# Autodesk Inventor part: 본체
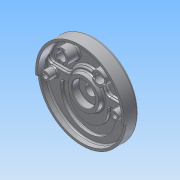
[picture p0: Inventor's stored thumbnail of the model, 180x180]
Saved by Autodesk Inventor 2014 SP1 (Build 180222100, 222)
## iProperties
Created: 2015-05
Part Number: 본체
Material: 알루미늄 6061
Document SubType Name: Modeling
Designer: 상담실
Density: 2.71 g/cm^3
Appearance: 알루미늄 - 평지
Mass: 1081.88 g
Surface Area: 1044.41 cm^2
Volume: 399.218 cm^3
Author: 상담실
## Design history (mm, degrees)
sketch "스케치1"
  geometry: C1 r 95 at (0, 0); 1 further point
  constraints: 1 centre point, 1 coincident
  dimensions: "d0" = 190 diameter of C1
extrude "돌출1" new body sketch "스케치1" distance "d1" = 32; taper "d2" = 0 deg
sketch "스케치2"
  geometry: C1 r 95 at (0, 0) reference; C2 r 90 at (0, 0)
  constraints: 1 centre point, 1 coincident
  dimensions: "d3" = 180 diameter of C2
extrude "돌출2" cut sketch "스케치2" distance "d4" = 25; taper "d5" = 0 deg
sketch "스케치3"
  geometry: L1 (-94.638, -8.28)-(-89.658, -7.844); L2 (89.658, -7.844)-(94.638, -8.28); L3 (-95, 0)-(95, 0); A1 r 90 centre (0, 0) between (-89.658, -7.844) and (89.658, -7.844) reference; A2 r 95 centre (0, 0) between (-94.638, -8.28) and (94.638, -8.28) reference; 2 further points
  constraints: 6 end point, 6 point on circle, 2 midpoint, 2 point on line, 1 coincident, 1 horizontal
  dimensions: "d6" = 5 deg angle of L3 L1; "d7" = 5 deg angle of L2 L3
extrude "돌출3" cut sketch "스케치3" distance "d8" = 5; taper "d9" = 0 deg
sketch "스케치4"
  geometry: L1 (-89.196, 12)-(-40.249, 12); L2 (40.249, 12)-(89.196, 12); A1 r 90 centre (0, 0) between (-89.196, 12) and (89.196, 12) reference; A2 r 42 centre (0, 0) between (40.249, 12) and (-40.249, 12)
  constraints: 4 end point, 4 point on circle, 2 horizontal, 1 centre point, 1 coincident, 1 collinear
  dimensions: "d10" = 84 diameter of A2; "d11" = 12 distance from line of A1.centre L1
extrude "돌출4" join sketch "스케치4" distance "d12" = 7; taper "d13" = 0 deg
sketch "스케치5"
  geometry: C1 r 35 at (0, 0); A1 r 42 centre (0, 0) between (40.249, 12) and (-40.249, 12) reference
  constraints: 1 centre point, 1 coincident
  dimensions: "d14" = 70 diameter of C1
extrude "돌출5" join sketch "스케치5" distance "d15" = 10; taper "d16" = -10 deg
sketch "스케치6"
  geometry: C1 r 95 at (0, 0) reference; C2 r 25 at (0, 0)
  constraints: 1 centre point, 1 coincident
  dimensions: "d17" = 50 diameter of C2
extrude "돌출6" join sketch "스케치6" distance "d18" = 12; taper "d19" = -15 deg
hole "구멍1" diameter "d22" = 23; stored, may be unused: countersink angle "d26" = 90 deg, drill point angle "d28" = 118 deg; dims "d20" = 10, "d21" = 10, "d23" = 6, "d24" = 4, "d25" = 2, "d27" = 8
fillet "모깎기1" dims "d31" = 10
fillet "모깎기2" dims "d32" = 3
fillet "모깎기3" dims "d33" = 5
sketch "스케치7"
  geometry: C1 r 9 at (-74, 0); C2 r 9 at (74, 0); A1 r 87 centre (0, 0) between (-86.059, 12.759) and (86.059, 12.759) reference
  constraints: 2 centre point, 2 horizontal alignment
  dimensions: "d34" = 18 diameter of C1; "d35" = 18 diameter of C2; "d36" = 148 distance of C2.centre C1.centre; "d37" = 74 distance of A1.centre C1.centre (= 0.5 x d36)
extrude "돌출7" join sketch "스케치7" distance "d38" = 18; taper "d39" = 0 deg
hole "구멍2" diameter "d42" = 11; stored, may be unused: countersink angle "d46" = 90 deg, drill point angle "d48" = 118 deg; dims "d40" = 10, "d41" = 10, "d43" = 6, "d44" = 4, "d45" = 2, "d47" = 8
hole "구멍3" diameter "d51" = 11; stored, may be unused: countersink angle "d55" = 90 deg, drill point angle "d57" = 118 deg; dims "d49" = 10, "d50" = 10, "d52" = 6, "d53" = 4, "d54" = 2, "d56" = 8
hole "구멍4" diameter "d60" = 18; stored, may be unused: countersink angle "d64" = 90 deg, drill point angle "d66" = 0 deg; dims "d61" = 6, "d62" = 4, "d63" = 2, "d65" = 11, "d67" = 10, "d68" = 10
hole "구멍5" diameter "d71" = 18; stored, may be unused: countersink angle "d75" = 90 deg, drill point angle "d77" = 0 deg; dims "d69" = 10, "d70" = 10, "d72" = 6, "d73" = 4, "d74" = 2, "d76" = 11
sketch "스케치8"
  geometry: C1 r 15 at (-40, 52); C2 r 15 at (40, 52); A1 r 45 centre (0, 0) between (40.774, 19.038) and (-40.774, 19.038) reference
  constraints: 2 centre point, 1 horizontal alignment
  dimensions: "d78" = 30 diameter of C1; "d79" = 30 diameter of C2; "d80" = 52 vertical distance of A1.centre C1.centre; "d81" = 80 distance of C2.centre C1.centre; "d82" = 40 horizontal distance of A1.centre C1.centre (= 0.5 x d81)
extrude "돌출8" join sketch "스케치8" distance "d83" = 25; taper "d84" = 0 deg
hole "구멍6" diameter "d87" = 20; stored, may be unused: countersink angle "d91" = 90 deg, drill point angle "d93" = 0 deg; dims "d85" = 10, "d86" = 10, "d88" = 6, "d89" = 4, "d90" = 2, "d92" = 11
hole "구멍7" diameter "d96" = 20; stored, may be unused: countersink angle "d100" = 90 deg, drill point angle "d102" = 0 deg; dims "d94" = 10, "d95" = 10, "d97" = 6, "d98" = 4, "d99" = 2, "d101" = 11
sketch "스케치9"
  geometry: L1 (-6, -15)-(6, -15); L2 (6, -15)-(6, 15); L3 (6, 15)-(-6, 15); L4 (-6, 15)-(-6, -15); L5 (-6, -15)-(6, 15); L6 (6, -15)-(-6, 15); L7 (65, -6)-(95, -6); L8 (95, -6)-(95, 6); L9 (95, 6)-(65, 6); L10 (65, 6)-(65, -6); L11 (65, -6)-(95, 6); L12 (95, -6)-(65, 6); C1 r 15 at (0, 0) reference; C2 r 10 at (80, 0) reference; 1 further point
  constraints: 24 end point, 4 midpoint, 4 parallel, 2 horizontal, 2 perpendicular
  dimensions: "d103" = 12 distance of L3.end L2.end; "d104" = 30 distance of L2.end L1.end; "d105" = 30 distance of L9.end L8.end; "d106" = 12 distance of L8.end L7.end
extrude "돌출9" cut sketch "스케치9" distance "d107" = 3; taper "d108" = 0 deg
sketch "스케치10"
  geometry: L1 (-76.916, 9)-(-74, 9) reference; L2 (-59, -19)-(-41, -19); L3 (41, -19)-(59, -19); L4 (-59, -19)-(-59, -14); L5 (-41, -14)-(-41, -19); L6 (41, -19)-(41, -14); L7 (59, -14)-(59, -19); C1 r 37.517 at (0, 0) reference; A1 r 59 centre (0, -19) between (-59, -19) and (59, -19); A2 r 41 centre (0, -19) between (-41, -19) and (41, -19); A3 r 9 centre (-50, -14) between (-41, -14) and (-59, -14); A4 r 9 centre (50, -14) between (59, -14) and (41, -14); 2 further points
  constraints: 12 end point, 8 point on circle, 8 tangent, 5 parallel, 4 centre point, 3 coincident, 1 horizontal alignment, 1 perpendicular, 1 vertical alignment
  dimensions: "d110" = 118 diameter of A1; "d111" = 82 diameter of A2; "d112" = 19 distance of C1.centre A1.centre; "d114" = 5 vertical distance of A1.centre A3.centre
extrude "돌출10" cut sketch "스케치10" distance "d115" = 7; taper "d116" = 0 deg
hole "구멍8" diameter "d119" = 50; stored, may be unused: countersink angle "d123" = 90 deg, drill point angle "d125" = 0 deg; dims "d117" = 10, "d118" = 10, "d120" = 6, "d121" = 4, "d122" = 2, "d124" = 15
chamfer "모따기1" distance "d126" = 1; stored, may be unused: second distance "d127" = 2, angle "d128" = 45 deg
sketch "스케치11"
  geometry: L1 (95, 0)-(-95, 0); L2 (47.244, 47.244)-(39.44, 39.44); L3 (-39.44, 39.44)-(-47.244, 47.244); C1 r 25 at (0, 0) reference; C2 r 90 at (0, 0) reference; A1 r 51 centre (0, 0) between (32.699, 39.138) and (-32.699, 39.138); A2 r 72 centre (0, 0) between (46.97, 54.569) and (-46.97, 54.569); A3 r 5 centre (-43.709, 50.78) between (-46.97, 54.569) and (-47.244, 47.244); A4 r 5 centre (-35.904, 42.975) between (-39.44, 39.44) and (-32.699, 39.138); A5 r 5 centre (35.904, 42.975) between (32.699, 39.138) and (39.44, 39.44); A6 r 5 centre (43.709, 50.78) between (47.244, 47.244) and (46.97, 54.569); 5 further points
  constraints: 16 point on circle, 8 tangent, 6 centre point, 6 end point, 6 point on line, 3 coincident, 3 equal radius, 1 horizontal, 1 midpoint
  dimensions: "d130" = 102 diameter of A1; "d131" = 190 distance of L1.start L1.end; "d133" = 45 deg angle of L2 L1; "d134" = 45 deg angle of L3 L1; "d135" = 72 radius of A2; "d144" = 5 radius of A3
extrude "돌출11" join sketch "스케치11" distance "d136" = 5; taper "d137" = 0 deg
fillet "모깎기6" dims "d143" = 3
fillet "모깎기7" dims "d145" = 5, "d146" = 3
sketch "스케치13"
  geometry: C1 r 68 at (0, 0); A1 r 67 centre (0, 0) between (43.709, 50.78) and (-43.709, 50.78) reference
  constraints: 1 centre point, 1 coincident, 1 other
  dimensions: "d147" = 136 diameter of C1
feature "엠보싱2" sketch "스케치13" dims "d0" = 190, "d8" = 5, "d9" = 0, "d148" = 0.5, "d149" = 0
fillet "모깎기8" dims "d150" = 0.3
fillet "모깎기9" dims "d151" = 3
fillet "모깎기10" dims "d152" = 1
fillet "모깎기11" dims "d153" = 3
fillet "모깎기12" dims "d154" = 3
node "솔리드1"
other parameters: "d129" = 144, "d132" = 72
